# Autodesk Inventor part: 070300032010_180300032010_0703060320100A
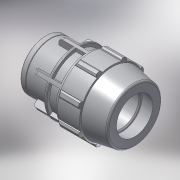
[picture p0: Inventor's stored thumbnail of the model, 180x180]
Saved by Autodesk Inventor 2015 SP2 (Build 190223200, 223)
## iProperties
Created: 2017-02
Part Number: 070300032010_180300032010_0703060320100A
Material: PVC-Piping
Description: PLASSON FEMALE ADAPTOR 32-1"
Document SubType Name: Modeling
Designer: KIM
Mass: 92.6774 g
Surface Area: 199.44 cm^2
Volume: 66.1981 cm^3
Density: 1.4 g/cm^3
Appearance: Smooth - White
Author: KIM
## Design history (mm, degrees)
derived "07030.ipt"
feature "Solid1::07030.ipt"
tag "TaggingFeature1"
body "Solid1"
other parameters: "d2" = 32, "d4" = 13.42857, "d5" = 23.5, "d7" = 64, "d9" = 13.42857, "d11" = 2.68571, "d12" = 51.2, "d13" = 120 deg, "d14" = 48, "d15" = 10 deg, "d16" = 57.6, "d18" = 1.6, "d19" = 35 deg, "d20" = 17.5 deg, "d21" = 59.52, "d23" = 0, "d25" = 360 deg, "d27" = 1.28, "d34" = 3.2, "d35" = 28.2, "d36" = 0, "d42" = 23.5, "d43" = 1.92, "d46" = 0.96, "d49" = 69, "d51" = 94, "d53" = 0.64, "d55" = 360 deg, "d61" = 21, "d62" = 25.6, "d63" = 30.291, "d64" = 31.33333, "d65" = 3.2, "d66" = 0.5, "d67" = 1, "d68" = 6.3, "d69" = 46.08, "d70" = 1.6, "d_" = 32, "E_" = 64, "H_" = 94, "l_" = 69, "l_2" = 21, "Rp_" = 30.291
